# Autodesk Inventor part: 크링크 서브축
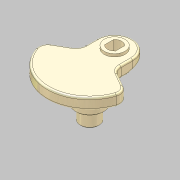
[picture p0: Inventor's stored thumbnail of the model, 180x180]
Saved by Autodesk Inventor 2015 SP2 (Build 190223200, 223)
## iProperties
Manager: KYOUNG IL JANG
Company: 한국ATC센터
Created: 2012-10
Part Number: 크링크 서브축
Document SubType Name: Modeling
Density: 1 g/cm^3
Checked By: KYOUNG IL JANG
Vendor: CBT Solutions
Designer: KYOUNG IL JANG
Material: 일반
Appearance: _시험_금속-티타늄(광택)
Author: KYOUNG IL JANG
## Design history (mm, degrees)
sketch "스케치1"
  geometry: L1 (-19, 109.368)-(-19, 91.368); L2 (-19, 91.368)-(-44.545, 76.619); L3 (19, 109.368)-(19, 91.368); L4 (19, 91.368)-(44.545, 76.619); C1 r 32.5 at (0, 83) reference; C2 r 10 at (0, 83); C3 r 17.5 at (0, 83); A1 r 45 centre (0, 83) between (-44.545, 76.619) and (44.545, 76.619); A2 r 32.5 centre (0, 83) between (-19, 109.368) and (19, 109.368); A3 r 19 centre (0, 109.368) between (19, 109.368) and (-19, 109.368); 1 further point
  constraints: 8 end point, 6 point on circle, 5 centre point, 4 coincident, 2 equal length, 1 horizontal alignment, 1 parallel, 1 tangent, 1 vertical, 1 vertical alignment
  dimensions: "d0" = 20 diameter of C2; "d1" = 35 diameter of C3; "d2" = 90 diameter of A1 (derived); "d3" = 65 diameter of A2 (derived); "d4" = 120 deg angle of L3 L4; "d5" = 19 radius of A3 (derived); "d6" = 18 distance of L1.start L1.end (derived)
  node "참조1"
extrude "돌출1" new body sketch "스케치1" distance "d7" = 12; taper "d8" = 0 deg
extrude "돌출2" join sketch "스케치1" distance "d9" = 5; taper "d10" = 0 deg
extrude "돌출3" join sketch "스케치1" distance "d11" = 41; taper "d12" = 0 deg
sketch "스케치2"
  geometry: C1 r 7.5 at (0, 109.368); C2 r 11 at (0, 109.368); A1 r 19 centre (0, 109.368) between (19, 109.368) and (-19, 109.368) reference; 1 further point
  constraints: 2 centre point, 2 coincident
  dimensions: "d13" = 15 diameter of C1; "d14" = 22 diameter of C2
extrude "돌출4" join sketch "스케치2" distance "d15" = 3; taper "d16" = 0 deg
extrude "돌출6" cut sketch "스케치2" stored distance "d19" = 10; taper "d20" = 0 deg
sketch "스케치3"
  geometry: L1 (-5.75, 4.815)-(-5.75, -4.815); L2 (5.75, 4.815)-(5.75, -4.815); A1 r 7.5 centre (0, 0) between (-5.75, 4.815) and (-5.75, -4.815) reference; 1 further point
  constraints: 4 end point, 4 point on circle, 2 parallel, 1 vertical
  dimensions: "d21" = 11.5 distance between parallel lines of L2 L1
extrude "돌출7" join sketch "스케치3" stored distance "d22" = 10; taper "d23" = 0 deg
sketch "스케치4"
  geometry: C1 r 10 at (0, 0) reference; C2 r 15 at (0, 0); 1 further point
  constraints: 1 centre point, 1 coincident
  dimensions: "d30" = 30 diameter of C2
extrude "돌출8" join sketch "스케치4" distance "d28" = 21; taper "d29" = 0 deg
chamfer "모따기1" distance "d31" = 1; stored, may be unused: second distance "d32" = 2, angle "d33" = 45 deg
sketch "스케치5"
  geometry: L1 (-19, 91.368)-(-19, 109.368) reference; L2 (19, 109.368)-(19, 91.368) reference; C1 r 9 at (0, 83); 3 further points
  constraints: 2 point on line, 1 centre point, 1 horizontal alignment
  dimensions: "d34" = 21 vertical distance of point (-19, 104) C1.centre (derived)
node "작업 평면1"
  node "작업축2"
sketch "스케치6"
  geometry: L1 (0, 50)-(38, 50); L2 (38, 50)-(38, 0); L3 (38, 0)-(0, 0); L4 (0, 0)-(0, 50); L5 (0, -12.202)-(0, 5.185) reference; L6 (38, 5.185)-(38, -12.202) reference; 2 further points
  constraints: 8 end point, 2 collinear, 1 point on line
  dimensions: "d37" = 50 distance from line of L1 L3.end
extrude "돌출9" cut sketch "스케치6" stored distance "d38" = 20.7; taper "d39" = 0 deg
fillet "모깎기1" dims "d26" = 10, "d27" = 2
node "솔리드1"
other parameters: "d35" = -15 deg (derived)
